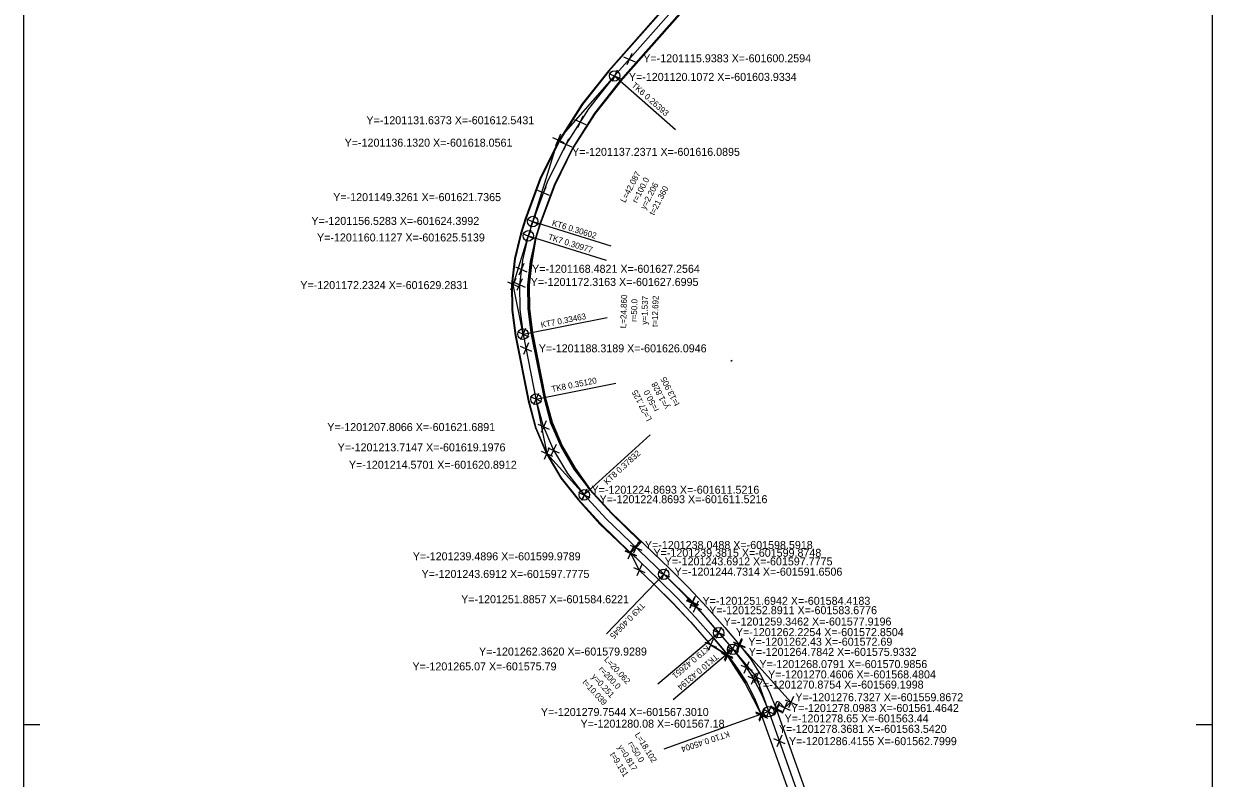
# Model space of a CAD drawing. Extents: x -601752 to -601455, y -1201912 to -1200862.
# Drawn here: x -601751.6 to -601454.6, y -1201295.7 to -1201107.1 of the extents above; entities that cross this region are included whole.
import ezdxf

# ---------------------------------------------------------------- set-up
doc = ezdxf.new("R2010")
doc.units = 0
for name, color, linetype in [('g_vytyceni oblouky', 7, 'Continuous'), ('g_vytyceni prejezd', 7, 'Continuous'), ('g_vytyceni příčné', 7, 'Continuous'), ('q_vytyceni prahy souradnice', 7, 'Continuous'), ('u_návrh', 7, 'Continuous'), ('u_oblouky', 7, 'Continuous'), ('u_osa', 7, 'Continuous'), ('u_popis oblouky', 7, 'Continuous'), ('u_rozšíření v obloucích', 7, 'Continuous'), ('x_rám', 7, 'Continuous')]:
    doc.layers.add(name, color=color, linetype=linetype)

msp = doc.modelspace()

# ---------------------------------------------------------------- linework, layer by layer
at = {"layer": 'g_vytyceni oblouky'}
for p, q in [((-601605.36, -1201119.47), (-601602.5, -1201120.74)), ((-601603.3, -1201118.68), (-601604.57, -1201121.54)), ((-601619.48, -1201135.5), (-601616.63, -1201136.76)), ((-601617.42, -1201134.7), (-601618.69, -1201137.56)), ((-601615.46, -1201135.81), (-601616.72, -1201138.67)), ((-601617.52, -1201136.6), (-601614.66, -1201137.87)), ((-601625.83, -1201155.9), (-601622.97, -1201157.16)), ((-601623.77, -1201155.1), (-601625.03, -1201157.96)), ((-601626.94, -1201159.48), (-601624.09, -1201160.75)), ((-601624.88, -1201158.68), (-601626.15, -1201161.54)), ((-601630.71, -1201171.6), (-601627.85, -1201172.86)), ((-601628.65, -1201170.8), (-601629.92, -1201173.66)), ((-601629.13, -1201171.68), (-601626.27, -1201172.95)), ((-601627.07, -1201170.89), (-601628.33, -1201173.75)), ((-601626.18, -1201183.25), (-601627.45, -1201186.11)), ((-601628.24, -1201184.05), (-601625.39, -1201185.32)), ((-601625.02, -1201200.3), (-601622.17, -1201201.56)), ((-601622.96, -1201199.5), (-601624.23, -1201202.36)), ((-601620.26, -1201213.14), (-601621.52, -1201216)), ((-601620.63, -1201213.08), (-601617.77, -1201214.35)), ((-601618.57, -1201212.29), (-601619.83, -1201215.14)), ((-601622.32, -1201213.94), (-601619.46, -1201215.2)), ((-601612.95, -1201224.24), (-601610.09, -1201225.5)), ((-601610.89, -1201223.44), (-601612.15, -1201226.3)), ((-601593.08, -1201244.1), (-601590.22, -1201245.36)), ((-601591.02, -1201243.3), (-601592.28, -1201246.16)), ((-601586.05, -1201251.25), (-601583.19, -1201252.52)), ((-601585.85, -1201251.06), (-601582.99, -1201252.33)), ((-601583.99, -1201250.46), (-601585.25, -1201253.31)), ((-601583.79, -1201250.27), (-601585.05, -1201253.12)), ((-601577.29, -1201257.92), (-601578.55, -1201260.77)), ((-601579.35, -1201258.71), (-601576.49, -1201259.98)), ((-601575.83, -1201262.85), (-601572.98, -1201264.12)), ((-601573.77, -1201262.06), (-601575.04, -1201264.91)), ((-601569.91, -1201269.83), (-601567.05, -1201271.09)), ((-601568.57, -1201269.45), (-601569.83, -1201272.3)), ((-601567.85, -1201269.03), (-601569.11, -1201271.89)), ((-601570.63, -1201270.24), (-601567.77, -1201271.51)), ((-601566.84, -1201278.45), (-601563.98, -1201279.71)), ((-601564.78, -1201277.65), (-601566.04, -1201280.51))]:
    msp.add_line(p, q, dxfattribs=at)
at = {"layer": 'g_vytyceni prejezd'}
for p, q in [((-601601.41, -1201238.86), (-601598.55, -1201240.12)), ((-601601.3, -1201238.75), (-601598.45, -1201240.01)), ((-601599.35, -1201238.06), (-601600.61, -1201240.92)), ((-601599.24, -1201237.95), (-601600.51, -1201240.81)), ((-601599.21, -1201243.06), (-601596.35, -1201244.32)), ((-601597.14, -1201242.26), (-601598.41, -1201245.12)), ((-601579.3, -1201260.93), (-601580.56, -1201263.79)), ((-601572.22, -1201260.8), (-601573.48, -1201263.65)), ((-601581.36, -1201261.73), (-601578.5, -1201262.99)), ((-601575.3, -1201263.36), (-601576.57, -1201266.21)), ((-601574.28, -1201261.59), (-601571.42, -1201262.86)), ((-601577.36, -1201264.15), (-601574.5, -1201265.42)), ((-601559.23, -1201275.3), (-601560.5, -1201278.16)), ((-601566.67, -1201278.33), (-601567.93, -1201281.18)), ((-601564.97, -1201277.74), (-601562.11, -1201279)), ((-601562.91, -1201276.94), (-601564.17, -1201279.8)), ((-601562.89, -1201277.47), (-601560.04, -1201278.73)), ((-601560.83, -1201276.67), (-601562.1, -1201279.53)), ((-601561.3, -1201276.1), (-601558.44, -1201277.37)), ((-601568.73, -1201279.12), (-601565.87, -1201280.39))]:
    msp.add_line(p, q, dxfattribs=at)
at = {"layer": 'g_vytyceni příčné'}
for p, q in [((-601601.69, -1201115.31), (-601598.83, -1201116.57)), ((-601599.63, -1201114.51), (-601600.89, -1201117.37)), ((-601611.91, -1201130.21), (-601613.18, -1201133.07)), ((-601613.97, -1201131), (-601611.11, -1201132.27)), ((-601621.1, -1201147.9), (-601622.37, -1201150.75)), ((-601623.17, -1201148.69), (-601620.31, -1201149.96)), ((-601628.69, -1201167.85), (-601625.83, -1201169.11)), ((-601626.62, -1201167.05), (-601627.89, -1201169.91)), ((-601627.52, -1201187.69), (-601624.67, -1201188.95)), ((-601625.46, -1201186.89), (-601626.73, -1201189.75)), ((-601623.12, -1201207.17), (-601620.26, -1201208.44)), ((-601621.06, -1201206.38), (-601622.32, -1201209.24)), ((-601612.96, -1201224.22), (-601610.11, -1201225.49)), ((-601610.9, -1201223.43), (-601612.17, -1201226.28)), ((-601597.96, -1201236.62), (-601599.22, -1201239.48)), ((-601600.02, -1201237.42), (-601597.16, -1201238.68)), ((-601583.05, -1201251.46), (-601584.31, -1201254.32)), ((-601585.11, -1201252.26), (-601582.25, -1201253.52)), ((-601570.35, -1201266.65), (-601571.62, -1201269.51)), ((-601572.41, -1201267.45), (-601569.56, -1201268.71)), ((-601564.23, -1201285.78), (-601561.37, -1201287.05)), ((-601562.17, -1201284.99), (-601563.43, -1201287.84))]:
    msp.add_line(p, q, dxfattribs=at)
at = {"layer": 'q_vytyceni prahy souradnice'}
for p, q in [((-601572.06, -1201261), (-601573.33, -1201263.86)), ((-601575.15, -1201263.65), (-601576.42, -1201266.5)), ((-601574.12, -1201261.79), (-601571.27, -1201263.06)), ((-601577.21, -1201264.44), (-601574.36, -1201265.71)), ((-601566.55, -1201278.65), (-601567.81, -1201281.51)), ((-601564.87, -1201278.02), (-601562.01, -1201279.28)), ((-601562.81, -1201277.22), (-601564.07, -1201280.08)), ((-601568.61, -1201279.44), (-601565.75, -1201280.71))]:
    msp.add_line(p, q, dxfattribs=at)
at = {"layer": 'u_návrh'}
for p, q in [((-601599.98, -1201239.49), (-601597.78, -1201243.69)), ((-601575.93, -1201264.78), (-601579.93, -1201262.36)), ((-601559.87, -1201276.73), (-601572.85, -1201262.23)), ((-601563.54, -1201278.37), (-601563.66, -1201277.12)), ((-601561.46, -1201278.1), (-601562.81, -1201276.73)), ((-601559.87, -1201276.73), (-601561.46, -1201278.1))]:
    msp.add_line(p, q, dxfattribs=at)
for points in [[(-601565.53, -1201037.03), (-601564.32, -1201044.14), (-601563.73, -1201049.01), (-601563.6, -1201053.96), (-601563.95, -1201058.86), (-601564.4, -1201062.61), (-601565.39, -1201068.28), (-601567.03, -1201073.84), (-601569.28, -1201079.19), (-601572.09, -1201084.21), (-601573.68, -1201086.7), (-601576.62, -1201091.08), (-601579.81, -1201095.32), (-601583.19, -1201099.37), (-601602.51, -1201121.29), (-601608.95, -1201129.42), (-601614.47, -1201138.14), (-601619.05, -1201147.4), (-601622.65, -1201157.12), (-601623.73, -1201160.61)], [(-601565.43, -1201036.71), (-601564.17, -1201044.12), (-601563.58, -1201049), (-601563.45, -1201053.97), (-601563.8, -1201058.87), (-601564.25, -1201062.63), (-601565.25, -1201068.31), (-601566.89, -1201073.89), (-601569.15, -1201079.26), (-601571.96, -1201084.29), (-601573.55, -1201086.79), (-601576.5, -1201091.17), (-601579.69, -1201095.42), (-601583.08, -1201099.47), (-601602.4, -1201121.39), (-601608.83, -1201129.51), (-601614.34, -1201138.22), (-601618.91, -1201147.46), (-601622.51, -1201157.17), (-601623.59, -1201160.65)], [(-601572.75, -1201077.5), (-601575.4, -1201082.24), (-601576.9, -1201084.6), (-601579.76, -1201088.85), (-601582.83, -1201092.93), (-601586.12, -1201096.86), (-601605.47, -1201118.82), (-601612.1, -1201127.19), (-601617.84, -1201136.26), (-601622.59, -1201145.87), (-601626.29, -1201155.88), (-601627.44, -1201159.58), (-601628.96, -1201165.79), (-601629.7, -1201172.21), (-601629.64, -1201178.67), (-601628.79, -1201185.01), (-601625.54, -1201201.39), (-601623.73, -1201208.12), (-601620.99, -1201214.62), (-601617.4, -1201220.68), (-601613.06, -1201226.15), (-601607.6, -1201232.16), (-601599.98, -1201239.49)], [(-601572.61, -1201077.56), (-601575.27, -1201082.31), (-601576.77, -1201084.68), (-601579.64, -1201088.94), (-601582.71, -1201093.02), (-601586, -1201096.96), (-601605.35, -1201118.92), (-601611.97, -1201127.28), (-601617.7, -1201136.33), (-601622.45, -1201145.93), (-601626.15, -1201155.93), (-601627.3, -1201159.62), (-601628.81, -1201165.82), (-601629.55, -1201172.22), (-601629.49, -1201178.66), (-601628.64, -1201184.99), (-601625.4, -1201201.35), (-601623.58, -1201208.08), (-601620.85, -1201214.55), (-601617.27, -1201220.6), (-601612.94, -1201226.05), (-601607.49, -1201232.05), (-601600.09, -1201239.17)], [(-601623.74, -1201160.66), (-601625.01, -1201166.5), (-601625.7, -1201172.42), (-601625.64, -1201178.38), (-601624.84, -1201184.35), (-601621.65, -1201200.47), (-601619.93, -1201206.82), (-601617.41, -1201212.81), (-601614.09, -1201218.41), (-601610.15, -1201223.62)], [(-601623.73, -1201160.61), (-601624.77, -1201166.55), (-601625.45, -1201172.44), (-601625.39, -1201178.37), (-601624.59, -1201184.31), (-601621.4, -1201200.42), (-601619.7, -1201206.74), (-601617.18, -1201212.7), (-601613.89, -1201218.26), (-601610.14, -1201223.64)], [(-601623.59, -1201160.65), (-601624.62, -1201166.57), (-601625.3, -1201172.44), (-601625.24, -1201178.36), (-601624.45, -1201184.29), (-601621.26, -1201200.38), (-601619.56, -1201206.69), (-601617.05, -1201212.63), (-601613.76, -1201218.18), (-601610.04, -1201223.52)], [(-601610.14, -1201223.64), (-601604.83, -1201229.47), (-601597.52, -1201236.51)], [(-601610.02, -1201223.54), (-601604.73, -1201229.37), (-601590.25, -1201243.3), (-601585.48, -1201248.06), (-601580.85, -1201252.98), (-601576.41, -1201258.04), (-601572.85, -1201262.23)], [(-601597.42, -1201236.4), (-601598.62, -1201237.64), (-601600.2, -1201239.28)], [(-601597.2, -1201236.61), (-601598.4, -1201237.85), (-601599.98, -1201239.49)], [(-601599.86, -1201239.4), (-601592.94, -1201246.05), (-601588.24, -1201250.74), (-601583.7, -1201255.57), (-601579.32, -1201260.56), (-601575.82, -1201264.69)], [(-601597.78, -1201243.69), (-601594.1, -1201247.23), (-601589.42, -1201251.89), (-601584.92, -1201256.68), (-601579.93, -1201262.36)], [(-601572.85, -1201262.23), (-601570, -1201265.91), (-601567.47, -1201269.88), (-601565.3, -1201274.05), (-601563.54, -1201278.37)], [(-601575.93, -1201264.78), (-601573.6, -1201268.45), (-601571.28, -1201272.08), (-601569.3, -1201275.9), (-601567.28, -1201279.79)], [(-601575.82, -1201264.69), (-601573.27, -1201268.22), (-601570.93, -1201271.88), (-601568.94, -1201275.73), (-601567.28, -1201279.79)], [(-601563.54, -1201278.37), (-601555.15, -1201301.93)], [(-601567.28, -1201279.79), (-601558.9, -1201303.32)]]:
    msp.add_lwpolyline(points, dxfattribs=at)
msp.add_arc((-601563.16, -1201277.08), 0.5, 44.379, 185.5276, dxfattribs=at)
at = {"layer": 'u_oblouky'}
for p, q in [((-601603.93, -1201120.11), (-601618.06, -1201136.13)), ((-601603.93, -1201120.11), (-601588.74, -1201133.49)), ((-601624.4, -1201156.53), (-601618.06, -1201136.13)), ((-601624.4, -1201156.53), (-601604.91, -1201162.59)), ((-601625.51, -1201160.11), (-601629.28, -1201172.23)), ((-601625.51, -1201160.11), (-601606.02, -1201166.17)), ((-601626.82, -1201184.68), (-601629.28, -1201172.23)), ((-601626.82, -1201184.68), (-601605.83, -1201180.52)), ((-601574.85, -1201191.48), (-601574.55, -1201191.21)), ((-601623.59, -1201200.93), (-601603.6, -1201196.97)), ((-601623.59, -1201200.93), (-601620.89, -1201214.57)), ((-601611.53, -1201224.86), (-601595.08, -1201209.89)), ((-601611.53, -1201224.86), (-601620.89, -1201214.57)), ((-601591.65, -1201244.73), (-601605.95, -1201259.58)), ((-601591.65, -1201244.73), (-601584.42, -1201251.69)), ((-601577.92, -1201259.35), (-601584.42, -1201251.69)), ((-601577.92, -1201259.35), (-601593.09, -1201272.23)), ((-601574.4, -1201263.49), (-601589.29, -1201276.12)), ((-601574.4, -1201263.49), (-601568.48, -1201270.46)), ((-601565.41, -1201279.08), (-601568.48, -1201270.46)), ((-601565.41, -1201279.08), (-601591.67, -1201288.43))]:
    msp.add_line(p, q, dxfattribs=at)
for centre in [(-601603.93, -1201120.11), (-601624.4, -1201156.53), (-601625.51, -1201160.11), (-601626.82, -1201184.68), (-601623.59, -1201200.93), (-601611.52, -1201224.87), (-601591.65, -1201244.73), (-601577.92, -1201259.35), (-601574.4, -1201263.49), (-601565.41, -1201279.08)]:
    msp.add_circle(centre, 1.31, dxfattribs=at)
at = {"layer": 'u_osa'}
msp.add_lwpolyline([(-601584.6, -1201098.17), (-601603.93, -1201120.11), (-601610.46, -1201128.35), (-601616.09, -1201137.24), (-601620.75, -1201146.66), (-601624.4, -1201156.53), (-601625.51, -1201160.11), (-601626.99, -1201166.15), (-601627.7, -1201172.32), (-601627.64, -1201178.53), (-601626.82, -1201184.68), (-601623.59, -1201200.93), (-601621.83, -1201207.47), (-601619.2, -1201213.72), (-601615.74, -1201219.55), (-601611.53, -1201224.86), (-601606.16, -1201230.76), (-601606.16, -1201230.76), (-601591.65, -1201244.73), (-601586.91, -1201249.45), (-601582.33, -1201254.32), (-601577.92, -1201259.35), (-601574.4, -1201263.49), (-601571.63, -1201267.06), (-601569.2, -1201270.88), (-601567.12, -1201274.89), (-601565.41, -1201279.08), (-601557.03, -1201302.63)], dxfattribs=at)
at = {"layer": 'u_rozšíření v obloucích'}
for points in [[(-601610.14, -1201223.64), (-601613.89, -1201218.26), (-601617.18, -1201212.7), (-601619.7, -1201206.74), (-601621.4, -1201200.42), (-601624.59, -1201184.31), (-601625.39, -1201178.37), (-601625.45, -1201172.44), (-601624.77, -1201166.55), (-601623.74, -1201160.66), (-601625.01, -1201166.5), (-601625.7, -1201172.42), (-601625.64, -1201178.38), (-601624.84, -1201184.35), (-601621.65, -1201200.47), (-601619.93, -1201206.82), (-601617.41, -1201212.81), (-601614.09, -1201218.41), (-601610.14, -1201223.64)], [(-601584.92, -1201256.68), (-601579.93, -1201262.36), (-601575.93, -1201264.78), (-601575.82, -1201264.69), (-601579.32, -1201260.56), (-601583.7, -1201255.57), (-601588.24, -1201250.74), (-601592.94, -1201246.05), (-601599.87, -1201239.38), (-601599.98, -1201239.49), (-601597.78, -1201243.69), (-601594.14, -1201247.19), (-601589.45, -1201251.86), (-601584.92, -1201256.68)], [(-601562.81, -1201276.73), (-601561.46, -1201278.1), (-601559.87, -1201276.73), (-601572.85, -1201262.23), (-601570, -1201265.91), (-601567.47, -1201269.88), (-601565.3, -1201274.05), (-601563.54, -1201278.37)], [(-601575.82, -1201264.69), (-601575.93, -1201264.78), (-601573.99, -1201267.83), (-601571.28, -1201272.08), (-601569.3, -1201275.9), (-601567.28, -1201279.79), (-601568.94, -1201275.73), (-601570.93, -1201271.88), (-601573.27, -1201268.22), (-601575.82, -1201264.69)], [(-601563.54, -1201278.37), (-601563.66, -1201277.12)]]:
    msp.add_lwpolyline(points, dxfattribs=at)
msp.add_arc((-601563.16, -1201277.08), 0.5, 44.379, 185.5276, dxfattribs=at)
at = {"layer": 'x_rám'}
for p, q in [((-601747.54, -1201282.35), (-601751.58, -1201282.35)), ((-601454.58, -1201282.35), (-601458.63, -1201282.35))]:
    msp.add_line(p, q, dxfattribs=at)
msp.add_lwpolyline([(-601454.58, -1200862.35), (-601454.58, -1201912.35), (-601751.58, -1201912.35), (-601751.58, -1200862.35)], close=True, dxfattribs=at)

# ---------------------------------------------------------------- texts
at = {"layer": 'g_vytyceni oblouky'}
for s, p in [('Y=-1201120.1072 X=-601603.9334', (-601600.37, -1201121.36)), ('Y=-1201136.1320 X=-601618.0561', (-601671.4, -1201137.81)), ('Y=-1201137.2371 X=-601616.0895', (-601614.55, -1201140.1)), ('Y=-1201156.5283 X=-601624.3992', (-601679.7, -1201157.37)), ('Y=-1201160.1127 X=-601625.5139', (-601678.3, -1201161.51)), ('Y=-1201172.2324 X=-601629.2831', (-601682.47, -1201173.42)), ('Y=-1201172.3163 X=-601627.6995', (-601624.91, -1201172.63)), ('Y=-1201213.7147 X=-601619.1976', (-601673.14, -1201213.99)), ('Y=-1201214.5701 X=-601620.8912', (-601670.33, -1201218.34)), ('Y=-1201224.8693 X=-601611.5216', (-601607.68, -1201226.96)), ('Y=-1201244.7314 X=-601591.6506', (-601588.96, -1201245.08)), ('Y=-1201251.8857 X=-601584.6221', (-601642.28, -1201251.97)), ('Y=-1201251.6942 X=-601584.4183', (-601581.97, -1201252.37)), ('Y=-1201259.3462 X=-601577.9196', (-601576.69, -1201257.55)), ('Y=-1201270.4606 X=-601568.4804', (-601565.58, -1201270.77)), ('Y=-1201270.8754 X=-601569.1998', (-601568.65, -1201273.31))]:
    msp.add_text(s, height=2, dxfattribs=at).set_placement(p)
at = {"layer": 'g_vytyceni prejezd'}
for s, p in [('Y=-1201239.4896 X=-601599.9789', (-601654.37, -1201241.24)), ('Y=-1201239.3815 X=-601599.8748', (-601594.22, -1201240.36)), ('Y=-1201243.6912 X=-601597.7775', (-601591.42, -1201242.5)), ('Y=-1201243.6912 X=-601597.7775', (-601652.17, -1201245.65)), ('Y=-1201262.2254 X=-601572.8504', (-601573.63, -1201260.19)), ('Y=-1201262.3620 X=-601579.9289', (-601637.81, -1201265.05)), ('Y=-1201264.7842 X=-601575.9332', (-601570.42, -1201265.13)), ('Y=-1201276.7327 X=-601559.8672', (-601558.76, -1201276.47)), ('Y=-1201279.7544 X=-601567.3010', (-601622.36, -1201280.17)), ('Y=-1201278.0983 X=-601561.4642', (-601559.84, -1201279.17)), ('Y=-1201278.3681 X=-601563.5420', (-601562.89, -1201284.38))]:
    msp.add_text(s, height=2, dxfattribs=at).set_placement(p)
at = {"layer": 'g_vytyceni příčné'}
for s, p in [('Y=-1201115.9383 X=-601600.2594', (-601596.77, -1201116.71)), ('Y=-1201131.6373 X=-601612.5431', (-601665.96, -1201132.2)), ('Y=-1201149.3261 X=-601621.7365', (-601674.25, -1201151.42)), ('Y=-1201168.4821 X=-601627.2564', (-601624.57, -1201169.35)), ('Y=-1201188.3189 X=-601626.0946', (-601622.88, -1201189.23)), ('Y=-1201207.8066 X=-601621.6891', (-601675.73, -1201208.92)), ('Y=-1201224.8693 X=-601611.5216', (-601609.71, -1201224.59)), ('Y=-1201238.0488 X=-601598.5918', (-601596.36, -1201238.4)), ('Y=-1201252.8911 X=-601583.6776', (-601580.29, -1201254.71)), ('Y=-1201268.0791 X=-601570.9856', (-601567.74, -1201268.18)), ('Y=-1201286.4155 X=-601562.7999', (-601560.36, -1201287.46))]:
    msp.add_text(s, height=2, dxfattribs=at).set_placement(p)
at = {"layer": 'q_vytyceni prahy souradnice'}
for s, p in [('Y=-1201262.43 X=-601572.69', (-601570.51, -1201262.59)), ('Y=-1201265.07 X=-601575.79', (-601654.44, -1201268.76))]:
    msp.add_text(s, height=2, dxfattribs=at).set_placement(p)
for s, p in [('Y=-1201280.08 X=-601567.18', (-601612.45, -1201283.09)), ('Y=-1201278.65 X=-601563.44', (-601561.46, -1201281.77))]:
    msp.add_text(s, height=2, rotation=360, dxfattribs=at).set_placement(p)
at = {"layer": 'u_oblouky'}
for s, rotation, p in [('L=42.087', 62.2586, (-601601.3, -1201151.95)), ('r=100.0', 62.2586, (-601598.38, -1201152.04)), ('y=2.206', 62.2586, (-601596.26, -1201153.65)), ('t=21.360', 62.2586, (-601594.06, -1201155.09)), ('L=24.860', 88.1782, (-601601.06, -1201183.23)), ('r=50.0', 88.1782, (-601598.39, -1201181.66)), ('y=1.537', 88.1782, (-601595.78, -1201182.33)), ('t=12.692', 88.1782, (-601593.17, -1201182.91)), ('t=13.905', 117.0521, (-601587.63, -1201202.17)), ('L=27.125', 117.0521, (-601594.54, -1201205.96)), ('y=1.828', 117.0521, (-601590.21, -1201202.89)), ('r=50.0', 117.0521, (-601592.81, -1201203.57)), ('L=20.062', 312.5849, (-601606.64, -1201266.14)), ('y=0.251', 312.5849, (-601609.81, -1201270.46)), ('r=200.0', 312.5849, (-601607.99, -1201268.55)), ('t=10.039', 312.5849, (-601612.1, -1201271.84)), ('L=18.102', 301.6326, (-601598.96, -1201284.83)), ('y=0.817', 301.6326, (-601603.21, -1201287.94)), ('r=50.0', 301.6326, (-601600.67, -1201287.06)), ('t=9.151', 301.6326, (-601605.16, -1201289.78))]:
    msp.add_text(s, height=1.5, rotation=rotation, dxfattribs=at).set_placement(p)
at = {"layer": 'u_popis oblouky'}
for s, rotation, p in [('TK6 0.26393', 318.6103, (-601599.82, -1201122.69)), ('KT6 0.30602', 342.9779, (-601619.7, -1201157.5)), ('TK7 0.30977', 342.7246, (-601620.66, -1201161)), ('KT7 0.33463', 11.2115, (-601622.23, -1201183.13)), ('TK8 0.35120', 11.2115, (-601619.55, -1201199.17)), ('KT8 0.37832', 42.3001, (-601605.82, -1201222.42)), ('TK9 0.40645', 226.0878, (-601597.28, -1201251.7)), ('KT9 0.42651', 220.2107, (-601580.93, -1201262.41)), ('TK10 0.43194', 220.2393, (-601578.79, -1201264.54)), ('KT10 0.45004', 198.0939, (-601575.49, -1201283.92))]:
    msp.add_text(s, height=1.5, rotation=rotation, dxfattribs=at).set_placement(p)

doc.saveas('drawing.dxf')
